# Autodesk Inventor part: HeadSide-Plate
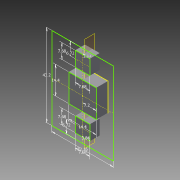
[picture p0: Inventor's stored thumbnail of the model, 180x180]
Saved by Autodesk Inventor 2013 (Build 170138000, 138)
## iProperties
Created: 2013-04
Part Number: HeadSide-Plate
Material: Generic
Document SubType Name: Modeling
Designer: frankenteddy
Density: 1 g/cm^3
Author: frankenteddy
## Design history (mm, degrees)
sketch "Sketch1"
  geometry: L1 (-16.08, 21.6)-(16.08, 21.6); L2 (16.08, 21.6)-(16.08, -21.6); L3 (16.08, -21.6)-(-16.08, -21.6); L4 (-16.08, -21.6)-(-16.08, 21.6); L5 (-3.84, 18.72)-(3.84, 18.72); L6 (3.84, 18.72)-(3.84, 11.04); L7 (3.84, 11.04)-(-3.84, 11.04); L8 (-3.84, 11.04)-(-3.84, 18.72); L9 (-3.84, -11.04)-(3.84, -11.04); L10 (3.84, -11.04)-(3.84, -18.72); L11 (3.84, -18.72)-(-3.84, -18.72); L12 (-3.84, -18.72)-(-3.84, -11.04); L13 (0, 21.6)-(0, -21.6); L14 (-7.2, 7.2)-(7.2, 7.2); L15 (7.2, 7.2)-(7.2, -7.2); L16 (7.2, -7.2)-(-7.2, -7.2); L17 (-7.2, -7.2)-(-7.2, 7.2); L18 (-3.84, 14.88)-(3.84, 14.88); L19 (-7.2, 0)-(7.2, 0); L20 (-3.84, -14.88)-(3.84, -14.88); L21 (-16.08, 0)-(16.08, 0); 1 further point
  constraints: 42 end point, 10 midpoint, 9 parallel, 4 horizontal, 4 perpendicular, 1 collinear
  dimensions: "d0" = 32.16 distance of L2.end L3.end; "d1" = 43.2 distance of L1.end L2.end; "d2" = 7.68 distance of L6.end L7.end; "d3" = 7.68 distance of L5.end L6.end; "d4" = 7.68 distance of L10.end L11.end; "d5" = 7.68 distance of L9.end L10.end; "d6" = 14.4 distance of L15.end L16.end; "d7" = 14.4 distance of L14.end L15.end; "d8" = 3.84 distance between parallel lines of L13 L8; "d9" = 7.2 distance between parallel lines of L13 L17; "d10" = 3.84 distance between parallel lines of L13 L12; "d11" = 6.72 distance between parallel lines of L20 L3; "d12" = 6.72 distance between parallel lines of L18 L1
extrude "Extrusion1" new body sketch "Sketch1" distance "d13" = 1.62; taper "d14" = 0 deg
extrude "Extrusion2" join sketch "Sketch1" distance "d15" = 5.12; taper "d16" = 0 deg
extrude "Extrusion3" join sketch "Sketch1" distance "d17" = 6.12; taper "d18" = 0 deg
sketch "Sketch3"
  geometry: L1 (-7.2, -7.2)-(7.2, -7.2) reference; L2 (7.2, -7.2)-(7.2, 7.2) reference; L3 (7.2, 7.2)-(-7.2, 7.2) reference; L4 (-7.2, 7.2)-(-7.2, -7.2) reference; L5 (0, 7.2)-(0, -7.2); 2 further points
  constraints: 2 end point, 2 midpoint, 1 coincident
workplane "Work Plane1"
sketch "Sketch4"
  geometry: L1 (-0.056, 7.5)-(-3.056, 7.5); L2 (-3.056, 7.5)-(-3.056, 15); L3 (-3.056, 15)-(-0.056, 15); L4 (-0.056, 15)-(-0.056, 7.5); L5 (4.944, 7.5)-(-3.056, 7.5); L6 (-3.056, 7.5)-(-3.056, 3.5); A1 r 5 centre (-0.056, 7.5) between (-3.056, 3.5) and (-3.056, 11.5); 2 further points
  constraints: 12 end point, 3 perpendicular, 3 point on circle, 2 parallel, 1 centre point, 1 coincident, 1 horizontal, 1 midpoint, 1 point on line, 1 other
  dimensions: "d22" = 3 distance of L2.end L3.end; "d23" = 7.5 distance of L1.end L2.end; "d24" = 10 diameter of A1
revolve "Revolution1" sketch "Sketch4" stored, may be unused: angle "d25" = 90 deg
sketch "Sketch5"
  geometry: L1 (-3.84, -18.72)-(3.84, -18.72) reference; L2 (3.84, -18.72)-(3.84, -11.04) reference; L3 (3.84, -11.04)-(-3.84, -11.04) reference; L4 (-3.84, -11.04)-(-3.84, -18.72) reference; L5 (-3.84, -11.04)-(3.84, -11.04); L6 (3.84, -11.04)-(3.84, -18.72); L7 (3.84, -18.72)-(-3.84, -18.72); L8 (-3.84, -18.72)-(-3.84, -11.04); L9 (0, -11.04)-(0, -18.72); L10 (-3.84, -14.88)-(3.84, -14.88); L11 (-1.84, -13.04)-(1.84, -13.04); L12 (1.84, -13.04)-(1.84, -16.72); L13 (1.84, -16.72)-(-1.84, -16.72); L14 (-1.84, -16.72)-(-1.84, -13.04); 1 further point
  constraints: 20 end point, 4 midpoint, 4 parallel, 2 horizontal, 2 perpendicular
  dimensions: "d26" = 2 distance between parallel lines of L11 L3; "d27" = 2 distance between parallel lines of L1 L13; "d28" = 2 distance between parallel lines of L2 L12; "d29" = 2 distance between parallel lines of L4 L14
extrude "Extrusion5" join sketch "Sketch5" distance "d30" = 2; taper "d31" = 0 deg
mirror "Mirror1"
extrude "Extrusion7" join sketch "Sketch1" distance "d34" = 3.12; taper "d35" = 0 deg
body "Solid1"
